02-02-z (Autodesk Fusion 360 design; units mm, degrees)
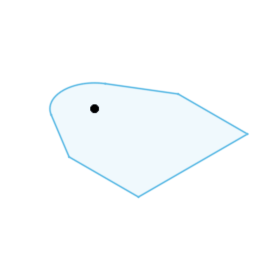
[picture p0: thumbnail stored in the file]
sketch "スケッチ" plane through (0, 0, 0) normal (0, 1, 0) x axis (1, 0, 0)
  line L1 (17.3949, 32.7065) -> (-9.8243, 16.2118)
  line L2 (58.999, 32.7065) -> (17.3949, 32.7065)
  line L3 (58.999, -32.7065) -> (58.999, 32.7065)
  line L4 (17.3949, -32.7065) -> (58.999, -32.7065)
  line L5 (-9.8243, -16.2118) -> (17.3949, -32.7065)
  arc A1 centre (0, 0) radius 18.9562 clockwise from (-9.8243, -16.2118) to (-9.8243, 16.2118)
  point P1 (0, 0)
  point P8 (0, 0)
  horizontal L2
  perpendicular L2 L3
  perpendicular L3 L4
  tangent L1 A1
  tangent L5 A1
  equal L1 L5
  equal L2 L4
  coincident P1 P8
